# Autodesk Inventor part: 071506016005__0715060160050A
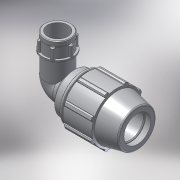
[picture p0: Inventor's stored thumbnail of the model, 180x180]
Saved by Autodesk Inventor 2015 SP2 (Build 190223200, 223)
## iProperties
Created: 2017-02
Part Number: 071506016005__0715060160050A
Material: PVC-Piping
Description: PLASSON 90° ELBOW FEMALE ADAPTOR 16-1/2"
Document SubType Name: Modeling
Designer: KIM
Mass: 92.6774 g
Surface Area: 199.44 cm^2
Volume: 66.1981 cm^3
Density: 1.4 g/cm^3
Appearance: Smooth - White
Author: KIM
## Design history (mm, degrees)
derived "07150.ipt"
feature "Solid1::07150.ipt"
tag "TaggingFeature1"
body "Solid1"
other parameters: "d2" = 16, "d4" = 5.5, "d5" = 16.5, "d7" = 39, "d9" = 9.42857, "d11" = 2.2, "d13" = 120 deg, "d14" = 24, "d15" = 12 deg, "d16" = 33.93, "d18" = 0.8, "d19" = 35 deg, "d20" = 17.5 deg, "d21" = 36.27, "d23" = 0, "d25" = 360 deg, "d27" = 0.78, "d33" = 0.32, "d42" = 24.42, "d43" = 1.17, "d46" = 0.48, "d51" = 66, "d68" = 2.2, "d72" = 39, "d73" = 24.2203, "d74" = 19, "d75" = 27.85335, "d76" = 18.631, "d77" = 20.9, "d79" = 7.4524, "d80" = 0.55893, "d83" = 0, "d84" = 0, "d91" = 29.25, "d94" = 18.631, "d95" = 13.0417, "d96" = 6.6, "d97" = 50 deg, "d98" = 16.7679, "d99" = 0.5, "d100" = 0.5, "d101" = 6.33333, "d102" = 24.2203, "d103" = 16.15, "d104" = 0, "d108" = 360 deg, "d110" = 0.72661, "d_" = 16, "E_" = 39, "A_" = 66, "l_2" = 19, "A_1" = 39, "Rp_" = 18.631, "d105" = 3.63304
